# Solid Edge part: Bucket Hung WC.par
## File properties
Title: BUCKET HUNG WC
Author: i.fialdini
Template: Iso Part.par
Last saved by: i.fialdini
Revision: 37
Application: Solid Edge
Stile della faccia: Model Default
Coef. of Thermal Exp: 0.0
Thermal Conductivity: 0.0
Specific Heat: 0.0
Modulus of Elasticity: 0.0
Poisson's Ratio: 0.0
Yield Stress: 0.0
Ultimate Stress: 0.0
Elongation: 0.0
Tipo di contenuto documento: 0
Accuracy: 0.990
Document Number: 8812
Revision: 0
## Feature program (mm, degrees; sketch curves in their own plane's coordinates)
lofted protrusion "unnamed LoftedProtrusion 1"
sketch for "unnamed Protrusion 1" plane through (-0.0064, 0, 0) normal (0, -1, 0) x-axis (1, 0, 0)
  line (252.5, -122.5) -> (182.475, -122.5)
  line (252.5, 122.5) -> (252.5, -122.5)
  line (182.475, 122.5) -> (252.5, 122.5)
extrude "unnamed Protrusion 1" add to key point along -normal
sketch for "ProtrusioneEstrusa_2" plane through (252.5, 140, 0) normal (1, 0, 0) x-axis (0, 0, 1)
  line (-122.5, -140) -> (-122.5, 125)
  line (-122.5, 125) -> (122.5, 125)
  line (122.5, -140) -> (122.5, 125)
  line (-122.5, -140) -> (122.5, -140)
extrude "ProtrusioneEstrusa_2" add finite 50 along +normal
lofted cutout "ScavoLoft_2"  EndTangentMagnitude1 = 1; StartTangentMagnitude1 = 1
fillet "Rotondo_1" radius 50
sketch for "unnamed Cutout 1" plane through (22.4777, 0, 0) normal (0, -1, 0) x-axis (0, 0, 1)
  arc centre (0, -20.0223) radius 135 from (135, -20.0223) to (-135, -20.0223) cw
  line (-135, -20.0223) -> (-135, 74.9777)
  arc centre (0, 74.9777) radius 135 from (-135, 74.9777) to (135, 74.9777) cw
  line (135, 74.9777) -> (135, -20.0223)
extrude "unnamed Cutout 1" cut finite 75 along -normal
sketch for "ScavoEstrusione_4" #1 plane through (0, 65, 0) normal (0, -1, 0) x-axis (-1, 0, 0)
sketch for "ScavoEstrusione_4" #2 plane through (0, 65, 0) normal (0, -1, 0) x-axis (-1, 0, 0)
extrude "ScavoEstrusione_4" cut to key point along -normal  Profile_Plane1_Distance = 10 mm
sketch for "ScavoEstrusione_5" plane through (9.9777, 130, 0) normal (0, -1, 0) x-axis (0, 0, 1)
  arc centre (0, -12.5223) radius 65 from (-65, -12.5223) to (65, -12.5223) cw
  line (65, -112.5223) -> (65, -12.5223)
  line (-65, -112.5223) -> (65, -112.5223)
  line (-65, -12.5223) -> (-65, -112.5223)
extrude "ScavoEstrusione_5" cut through along -normal  Treatment1_DraftAngle = 10 deg
sketch for "ScavoEstrusione_6" plane through (0, 75, 0) normal (0, -1, 0) x-axis (-1, 0, 0)
  arc centre (52.5, 0) radius 163 from (52.5, 163) to (52.5, -163) cw
  line (52.5, -163) -> (-52.5, -163)
  arc centre (-52.5, 0) radius 163 from (-52.5, -163) to (-52.5, 163) cw
  line (-52.5, 163) -> (52.5, 163)
extrude "ScavoEstrusione_6" cut to key point along -normal  Treatment1_DraftAngle = 10 deg
fillet "Rotondo_9" radius 50  VertexRadius1 = 50 mm; VertexRadius2 = 70 mm; VertexRadius3 = 70 mm; VertexRadius4 = 150 mm; VertexRadius5 = 182 mm; VertexRadius6 = 150 mm
fillet "Rotondo_12" radius 16
fillet "Rotondo_14" radius 16
fillet "Rotondo_10" radius 70
sketch for "ScavoEstrusione_7" plane through (57.4962, 280, 0) normal (0, 1, 0) x-axis (-1, 0, 0)
  line (129.9962, 105) -> (-213.0038, 105)
  line (-213.0038, 105) -> (-213.0038, -105)
  line (129.9962, -105) -> (-213.0038, -105)
extrude "ScavoEstrusione_7" cut finite 72 along -normal
sketch for "ProtrusioneEstrusa_3" plane through (50.5, 208, 0) normal (0, 1, 0) x-axis (0, 0, -1)
  line (0, 0) -> (0, 0)
  line (-63.4205, 21.5267) -> (-52.7261, -83.249)
  line (63.4205, 21.5267) -> (52.7261, -83.249)
extrude "ProtrusioneEstrusa_3" add finite 130 along +normal  Treatment1_DraftAngle = 5 deg
sketch for "ScavoEstrusione_8" plane through (70, 208, 0) normal (0, -1, 0) x-axis (0, 0, 1)
  line (-51.2465, -22.9896) -> (-51.2465, 47.5)
  arc centre (0, 47.5) radius 51.2465 from (-51.2465, 47.5) to (51.2465, 47.5) cw
  line (51.2465, 47.5) -> (51.2465, -22.9896)
  line (35.4896, -38.7465) -> (-35.4896, -38.7465)
extrude "ScavoEstrusione_8" cut finite 125 along -normal
sketch for "unnamed Protrusion 2" #1 plane through (57.4962, 280, 0) normal (0, 1, 0) x-axis (-1, 0, 0)
  line (-27.9639, 46.2223) -> (-27.9639, 105)
  line (-17.9639, 105) -> (-27.9639, 105)
  line (-17.9639, 47.243) -> (-17.9639, 105)
  line (-27.9639, 46.2223) -> (-17.9639, 47.243)
sketch for "unnamed Protrusion 2" #2 plane through (57.4962, 280, 0) normal (0, 1, 0) x-axis (-1, 0, 0)
  line (-27.9639, -105) -> (-27.9639, -46.2223)
  line (-27.9639, -46.2223) -> (-17.9639, -47.243)
  line (-17.9639, -105) -> (-17.9639, -47.243)
  line (-27.9639, -105) -> (-17.9639, -105)
  dimension (linear) = 17.9639
extrude "unnamed Protrusion 2" add to key point along -normal
replace surface "unnamed ReplaceSurface 1"
sketch for "ProtrusioneEstrusa_6" plane through (286.5, 145, 0) normal (1, 0, 0) x-axis (0, 0, -1)
extrude "ProtrusioneEstrusa_6" add to key point symmetric  Profile_Plane1_Distance = 16 mm
sketch for "ScavoEstrusione_9" plane through (302.5, 161.25, 0) normal (1, 0, 0) x-axis (0, 0, -1)
  line (70, -4.9106) -> (72.8284, -7.7391)
  line (72.8284, -7.7391) -> (90.3284, 27.4216)
  line (87.5, 30.25) -> (90.3284, 27.4216)
  line (87.5, 30.25) -> (79.814, 59.6299)
  line (-87.5, 30.25) -> (-79.814, 59.6299)
  line (-87.5, 30.25) -> (-90.3284, 27.4216)
  line (-73.2766, -7.2049) -> (-90.3284, 27.4216)
  line (-70, -4.9106) -> (-73.2766, -7.2049)
  arc centre (0, 38.75) radius 82.5 from (70, -4.9106) to (-70, -4.9106) cw
extrude "ScavoEstrusione_9" cut finite 34 along -normal  Treatment1_DraftAngle = 3 deg
sketch for "unnamed Protrusion 3" #1 plane through (268.5, 161.8591, -0.002) normal (1, 0, 0) x-axis (0, 0, -1)
  circle centre (-0.002, 38.1409) radius 40.5
sketch for "unnamed Protrusion 3" #2 plane through (268.5, 161.8591, -0.002) normal (1, 0, 0) x-axis (0, 0, -1)
  circle centre (-0.002, 38.1409) radius 50
extrude "unnamed Protrusion 3" add through along -normal
fillet "Rotondo_16" radius 31
sketch for "ScavoEstrusione_11" plane through (268.5, 180.6091, -0.002) normal (1, 0, 0) x-axis (0, 0, -1)
  line (61.3538, 27.3909) -> (61.3538, -33.0579)
  arc centre (-0.002, 19.3909) radius 80.7181 from (-61.3579, -33.0579) to (61.3538, -33.0579) ccw
  line (-61.3579, 27.3909) -> (-61.3579, -33.0579)
  line (-49.3579, 27.3909) -> (-61.3579, 27.3909)
  line (49.3538, 27.3909) -> (61.3538, 27.3909)
  dimension (linear) = 49.3538
extrude "ScavoEstrusione_11" cut finite 60 along -normal
sketch for "ScavoEstrusione_12" plane through (268.5, 200, 0) normal (1, 0, 0) x-axis (0, 0, -1)
  circle centre (0, 0) radius 40.5
extrude "ScavoEstrusione_12" cut finite 140 along -normal
sketch for "unnamed Cutout 2" plane through (268.5, 161.8591, -0.002) normal (1, 0, 0) x-axis (0, 0.895244, -0.445577)
  line (12.9968, 77.4403) -> (-5.4791, 114.5617)
  line (-5.4791, 114.5617) -> (-57.2714, 88.7839)
  line (-38.7955, 51.6625) -> (-57.2714, 88.7839)
  line (12.9968, 77.4403) -> (-38.7955, 51.6625)
extrude "unnamed Cutout 2" cut to key point along -normal
extrude "unnamed Cutout 3" cut finite 182.8698
delete faces "unnamed DeleteFaces 1"
delete faces "unnamed DeleteFaces 2"
sketch for "ScavoEstrusione_18" plane through (0, 0, 0) normal (0, 0, 1) x-axis (1, 0, 0)
  line (161.8291, 240.5) -> (161.8291, 291.437)
  arc centre (143.5477, 291.437) radius 18.2814 from (143.5477, 309.7184) to (161.8291, 291.437) cw
  line (143.5477, 309.7184) -> (120.4206, 309.7184)
  line (120.4206, 309.7184) -> (117.9724, 275.4973)
  line (153.573, 275.4973) -> (117.9724, 275.4973)
  line (153.573, 240.5) -> (153.573, 275.4973)
extrude "ScavoEstrusione_18" cut finite 50 symmetric
sketch for "ProtrusioneEstrusa_8" plane through (143.2071, 275.4973, 0) normal (0, 1, 0) x-axis (-1, 0, 0)
  line (10.3659, 25) -> (10.3659, -25)
  line (10.3659, -25) -> (2.7802, -25)
  line (2.7802, 25) -> (2.7802, -25)
  line (10.3659, 25) -> (2.7802, 25)
extrude "ProtrusioneEstrusa_8" add finite 26.8745 along +normal  Treatment1_DraftAngle = 5 deg
fillet "Rotondo_17" radius 32
fillet "Rotondo_18" radius 10
fillet "Rotondo_19" radius 10
sketch for "unnamed Cutout 4" plane through (208.5, 163.6409, -1.2972) normal (1, 0, 0) x-axis (0, 1, 0)
extrude "unnamed Cutout 4" cut along +normal
sketch for "unnamed Cutout 5" plane through (42.4081, 176.3301, 61.3559) normal (0, 0, -1) x-axis (-1, 0, 0)
extrude "unnamed Cutout 5" cut to key point along -normal
sketch for "unnamed Cutout 6" plane through (207.98, 208, 77.1779) normal (0, 1, 0) x-axis (0, 0, -1)
  line (15.8221, -0.52) -> (15.8221, -60.52)
  line (-4.1637, -60.52) -> (15.8221, -60.52)
  line (-4.1637, -60.52) -> (-4.2721, -62.52)
  line (-27.8221, -62.52) -> (-4.2721, -62.52)
  line (-27.8221, 122.52) -> (-27.8221, -62.52)
  line (3.1026, 122.52) -> (-27.8221, 122.52)
  line (3.1026, -0.52) -> (3.1026, 122.52)
  line (15.8221, -0.52) -> (3.1026, -0.52)
extrude "unnamed Cutout 6" cut to key point along -normal
sketch for "ScavoEstrusione_22" #1 plane through (302.5, 161.25, 0) normal (1, 0, 0) x-axis (0, 0, -1)
  circle centre (-104.5, -128.25) radius 5.5
sketch for "ScavoEstrusione_22" #2 plane through (302.5, 161.25, 0) normal (1, 0, 0) x-axis (0, 0, -1)
  circle centre (-46.5, -128.25) radius 5.5
sketch for "ScavoEstrusione_22" #3 plane through (302.5, 161.25, 0) normal (1, 0, 0) x-axis (0, 0, -1)
  circle centre (104.5, -128.25) radius 5.5
sketch for "ScavoEstrusione_22" #4 plane through (302.5, 161.25, 0) normal (1, 0, 0) x-axis (0, 0, -1)
  circle centre (46.5, -128.25) radius 5.5
extrude "ScavoEstrusione_22" cut finite 61.2404 along -normal
sketch for "unnamed Cutout 7" plane through (302.5, 161.25, 0) normal (1, 0, 0) x-axis (0, 0, -1)
  circle centre (0, -96.25) radius 27.5
extrude "unnamed Cutout 7" cut finite 38 along -normal
sketch for "unnamed Cutout 8" plane through (264.5, 58, 0) normal (1, 0, 0) x-axis (0, 0, -1)
  circle centre (0, 7) radius 24
extrude "unnamed Cutout 8" cut finite 83.5391 along -normal
sketch for "unnamed Cutout 9" plane through (302.5, 161.25, 0) normal (1, 0, 0) x-axis (0, 0, 1)
  circle centre (-90, 66.25) radius 15
extrude "unnamed Cutout 9" cut finite 45.9218 along -normal
mirror "unnamed Mirror 1" of "unnamed Cutout 9" about plane through (0, 0, 0) normal (0, 0, -1)
sketch for "unnamed Cutout 10"
  line (-16.6741, 82.3995) -> (-16.6741, 92.52)
  line (-16.6741, 92.52) -> (-30.5, 92.52)
  line (-30.5, 92.52) -> (-30.5, 69.3993)
  line (-30.5, 69.3993) -> (11.0781, 64.0675)
extrude "unnamed Cutout 10" cut finite 45.9218
sketch for "ScavoEstrusione_27" plane through (302.5, 161.25, 0) normal (1, 0, 0) x-axis (0, 0, 1)
  line (-98.9992, -118.75) -> (-98.9992, 41.8571)
  line (-98.9992, 90.6429) -> (-98.9992, 112.6939)
  line (-89.5584, 135.25) -> (-63.9893, 135.25)
  arc centre (-15.9184, 117.2217) radius 13.6712 from (-24.184, 128.1112) to (-28.7789, 121.8594) ccw
  arc centre (15.9184, 117.2217) radius 13.6712 from (28.7789, 121.8594) to (24.184, 128.1112) ccw
  line (63.9893, 135.25) -> (89.5584, 135.25)
  arc centre (104.5, 128.25) radius 16.5 from (89.5584, 135.25) to (98.9992, 112.6939) ccw
  line (98.9992, 112.6939) -> (98.9992, 90.6429)
  arc centre (90, 66.25) radius 26 from (98.9992, 90.6429) to (97.3952, 41.3239) ccw
  line (97.3952, -116.4928) -> (97.3952, 41.3239)
extrude "ScavoEstrusione_27" cut finite 6 along -normal
sketch for "ScavoEstrusione_28" plane through (296.5, 166.25, 0) normal (1, 0, 0) x-axis (0, 1, 0)
  line (-101.25, 40) -> (-38.0446, 40)
  line (-101.25, -40) -> (-38.0446, -40)
extrude "ScavoEstrusione_28" cut finite 8 along +normal
sketch for "unnamed Cutout 11" plane through (296.5, 166.25, 0) normal (1, 0, 0) x-axis (0, 1, 0)
  line (-101.25, 38) -> (-39.1229, 38)
  line (-101.25, -38) -> (-39.1229, -38)
extrude "unnamed Cutout 11" cut finite 8 along -normal
multibody boolean "unnamed MultibodyBoolean 1"
delete faces "unnamed DeleteFaces 3"
body pattern "unnamed BodyPattern 1"
pattern "unnamed Pattern 1"
delete faces "unnamed DeleteFaces 4"
extrude "unnamed Cutout 12" cut finite 46.2385
extrude "unnamed Cutout 13" cut
sketch for "unnamed Cutout 14" plane through (207.98, 177.5, 105) normal (0, 0, -1) x-axis (0, -1, 0)
extrude "unnamed Cutout 14" cut
extrude "unnamed Cutout 15" cut finite 46.2385
sketch for "unnamed Cutout 16" plane through (57.4963, 280, 0) normal (0, 1, 0) x-axis (1, 0, 0)
extrude "unnamed Cutout 16" cut finite 9 along -normal
sketch for "ScavoEstrusione_42" plane through (57.4963, 280, 0) normal (0, 1, 0) x-axis (-1, 0, 0)
  circle centre (244.9963, 0) radius 7
  dimension (linear) = 244.9963
extrude "ScavoEstrusione_42" cut finite 100 along -normal
fillet "unnamed Round 1"
fillet "Rotondo_33" radius 50
fillet "Rotondo_34" radius 50
fillet "Rotondo_35" radius 3
fillet "Rotondo_36" radius 2
fillet "Rotondo_38" radius 3
fillet "Rotondo_41" radius 40
fillet "Rotondo_42" radius 3
fillet "Rotondo_43" radius 3
fillet "Rotondo_44" radius 4
fillet "Rotondo_45" radius 14
fillet "Rotondo_46" radius 5
fillet "Rotondo_47" radius 5
replace surface "unnamed ReplaceSurface 2"
replace surface "unnamed ReplaceSurface 3"
fillet "unnamed Round 2"
fillet "Rotondo_50" radius 30
fillet "Rotondo_24" radius 3.5
fillet "Rotondo_51" radius 2
Other named dimensions: "Spostamento_faccia_7": Distance = 28.4846 mm | "Spostamento_faccia_8": Distance = 32.9027 mm
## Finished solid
Body 1: sheet body, 1 face, 9 edges, 9 vertices.
  Faces by surface: plane 1
  Edges by curve: line 8, intersection 1
Body 2: sheet body, 12 faces, 53 edges, 41 vertices.
  Faces by surface: cylinder 4, plane 3, cone 2, torus 2, blend 1
  Edges by curve: line 21, intersection 15, circle 13, curve on surface 3, ellipse 1
Body 3: sheet body, 39 faces, 111 edges, 72 vertices.
  Faces by surface: blend 12, offset 10, plane 8, cylinder 5, cone 3, torus 1
  Edges by curve: line 39, intersection 36, curve on surface 20, circle 16
Body 4: sheet body, 2 faces, 5 edges, 4 vertices.
  Faces by surface: spline 2
  Edges by curve: spline 3, circle 2
Body 5: solid body, 392 faces, 928 edges, 536 vertices.
  Faces by surface: cylinder 137, plane 88, torus 70, blend 62, spline 18, cone 8, sphere 6, swept 2, offset 1
  Edges by curve: line 335, circle 327, intersection 187, curve on surface 36, ellipse 34, spline 9
Bounding box of the edges (mm; curved faces can reach further): 534.780 x 338.000 x 349.253, from (-232.28, 0, -174.6265) to (302.5, 338, 174.6265).
Cylindrical faces by radius (mm): R2 x33, R3 x23, R3.5 x14, R4 x8, R5 x8, R5.5 x4, R7 x1, R10 x2, R15 x2, R16 x2, R16.5 x2, R18.2814 x1, R18.8382 x2, R21 x5, R24 x1, R25 x2, R26 x2, R27.5 x1, R28.5 x1, R30 x2, R31 x7, R36 x3, R38 x1, R40 x1, R40.5 x1, R50 x2, R80.7181 x1, R105 x1, R110 x1, R135 x2, R155 x3, R163 x3, R241.7384 x2, R289.5448 x2
Conical faces (half-angle, radius in mm at the cone's reference point): 3 deg R82.5 x2, 5 deg R51.2465 x1, 5 deg R53 x2, 5 deg R56.2275 x1, 5 deg R63.75 x2, 10 deg R65 x1, 10 deg R69.924 x1, 10 deg R163 x2, 10 deg R167.924 x1
Toroidal faces (ring radius, tube radius in mm): R1 r2 x2, R2 r2 x12, R3 r3 x8, R4 r2 x2, R4 r4 x2, R11.9041 r31 x1, R11.9041 r36 x1, R13.2202 r31 x2, R14.5 r2 x2, R16.8382 r2 x2, R18.5 r2 x2, R20.8382 r2 x2, R23.9702 r31 x2, R24 r2 x2, R25.5 r3 x1, R26.5 r3.5 x4, R28 r2 x2, R28.5 r3.5 x4, R29.5 r2 x1, R31.5 r3 x1, R36 r2 x1, R40 r2 x1, R42 r2 x1, R43.5 r3 x1, R47 r3 x1, R72.5 r32 x1, R83.6642 r2 x1, R84.0835 r2 x3, R107 r2 x1, R107 r3 x2, R108 r3 x2, R138 r3 x2, R286.0448 r3.5 x1
Spherical faces by radius (mm): R2 x2, R3 x2, R5 x2
Planar faces by outward normal: +x 17, +y 14, +z 11, -x 4, -y 6, -z 11, oblique 25
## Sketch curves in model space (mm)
circle centre (268.5, 200, 0) radius 50
circle centre (268.5, 200, 0) radius 40.5
arc centre (-72.5, 208, 0) radius 105 from (-94.0324, 208, -102.7684) through (-177.3153, 208, 6.2245) to (-94.0324, 208, 102.7684)
arc centre (-72.5, 208, 0) radius 107 from (-94.0492, 208, -104.8076) through (-178.1099, 208, 17.1914) to (-72.5, 208, 107)
line (-72.5, 208, 107) -> (105.4601, 208, 107)
arc centre (-72.5, -192.9169, 1.9819) radius 414.4432 from (-72.5, 208, 107) through (-72.5, 218.2562, 53.9417) to (-72.5, 221.5216, 0)
line (-72.5, 221.5263, 1.9819) -> (-72.5, 187.8446, 1.9819)
arc centre (75.4601, -192.9169, 1.9819) radius 414.4432 from (75.4601, 208, 107) through (75.4601, 218.2562, 53.9417) to (75.4601, 221.5216, 0)
line (75.4601, 221.5216, 0) -> (75.4601, 183.9526, 0)
arc centre (128.3673, 208, 0) radius 53 from (133.749, 208, -52.7261) through (181.272, 208, 3.1761) to (133.749, 208, 52.7261)
line (28.9733, 208, -63.4205) -> (133.749, 208, -52.7261)
arc centre (22.5, 208, 0) radius 63.75 from (28.9733, 208, 63.4205) through (-41.2216, 208, -1.9037) to (28.9733, 208, -63.4205)
line (28.9733, 208, 63.4205) -> (133.749, 208, 52.7261)
line (52.5, 75, -163) -> (-52.5, 75, -163)
arc centre (-52.5, 75, 0) radius 163 from (-52.5, 75, -163) through (-215.4284, 75, 4.8302) to (-52.5, 75, 163)
line (-52.5, 75, 163) -> (52.5, 75, 163)
arc centre (52.5, 75, 0) radius 163 from (52.5, 75, 163) through (215.4284, 75, -4.8302) to (52.5, 75, -163)
line (122.5, 130, 65) -> (22.5, 130, 65)
arc centre (22.5, 130, 0) radius 65 from (22.5, 130, -65) through (-42.4715, 130, 1.9262) to (22.5, 130, 65)
line (22.5, 130, -65) -> (122.5, 130, -65)
line (122.5, 130, -65) -> (122.5, 130, 65)
line (-52.5, 0, 135) -> (52.5, 0, 135)
arc centre (52.5, 0, 0) radius 135 from (52.5, 0, 135) through (187.4407, 0, -4.0005) to (52.5, 0, -135)
line (52.5, 0, -135) -> (-52.5, 0, -135)
arc centre (-52.5, 0, 0) radius 135 from (-52.5, 0, -135) through (-187.4407, 0, 4.0005) to (-52.5, 0, 135)
line (252.5, 0, -122.5) -> (182.475, 0, -122.5)
line (252.5, 0, 122.5) -> (252.5, 0, -122.5)
line (182.475, 0, 122.5) -> (252.5, 0, 122.5)
arc centre (67.5, 280, 0) radius 150 from (67.5, 280, 150) through (217.4341, 280, -4.445) to (67.5, 280, -150)
line (67.5, 280, -150) -> (-67.5, 280, -150)
arc centre (-67.5, 280, 0) radius 150 from (-67.5, 280, -150) through (-217.4341, 280, 4.445) to (-67.5, 280, 150)
line (-67.5, 280, 150) -> (67.5, 280, 150)
arc centre (57.5, 0, 0) radius 175 from (57.5, 0, 175) through (232.4231, 0, -5.1858) to (57.5, 0, -175)
line (57.5, 0, -175) -> (-57.5, 0, -175)
arc centre (-57.5, 0, 0) radius 175 from (-57.5, 0, -175) through (-232.4231, 0, 5.1858) to (-57.5, 0, 175)
line (-57.5, 0, 175) -> (57.5, 0, 175)
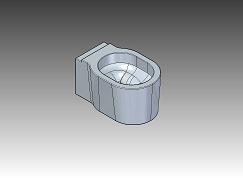
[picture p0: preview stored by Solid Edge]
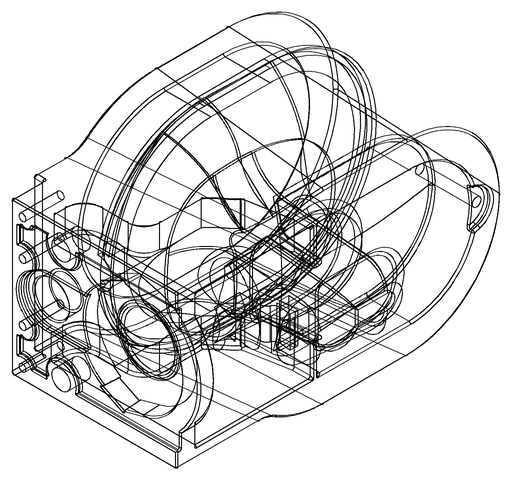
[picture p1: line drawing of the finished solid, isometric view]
